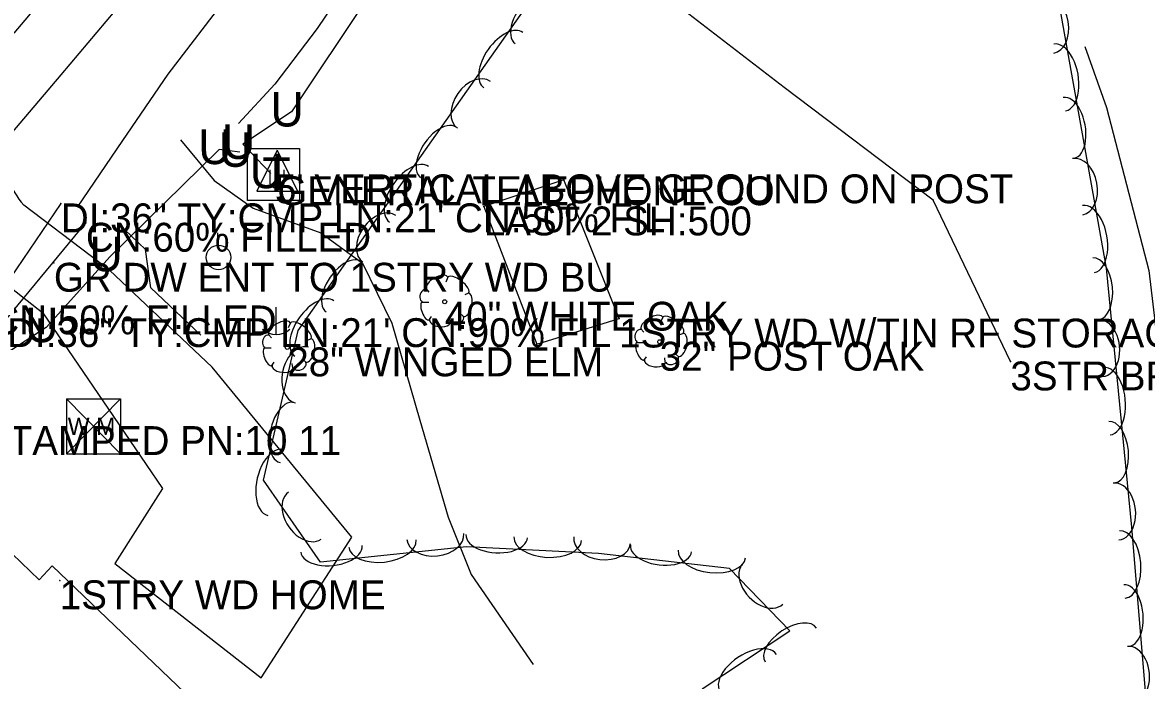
# Model space of a CAD drawing. Extents: x 1451369 to 1458940, y 1868647 to 1875095.
# Drawn here: x 1454748.2 to 1454943, y 1871712 to 1871825.9 of the extents above; entities that cross this region are included whole.
import ezdxf

# ---------------------------------------------------------------- set-up
doc = ezdxf.new("R2010")
doc.units = 0
for name, color, linetype in [('Default', 7, 'Continuous'), ('E_Const Align', 7, 'Continuous'), ('E_Label', 7, 'Continuous'), ('E_PL and Hook', 7, 'Continuous'), ('E_Property Line', 7, 'Continuous'), ('E_Proposed ROW and Easements', 7, 'Continuous'), ('E_Quarter Section Line', 7, 'Continuous'), ('E_Row Point', 7, 'Continuous'), ('E_ROW Point Number', 7, 'Continuous'), ('E_Survey Point', 7, 'Continuous'), ('E_Survey Point Number', 7, 'Continuous'), ('E_Tract Number', 7, 'Continuous'), ('S_BUILDING_ANNOT', 7, 'Continuous'), ('S_EDGE_PAVEMENT', 7, 'Continuous'), ('S_EXIST_ROW', 7, 'Continuous'), ('S_FENCE_ANNOT', 7, 'Continuous'), ('S_PARKING', 7, 'Continuous'), ('S_PAVEMENT_CROWN', 7, 'Continuous'), ('S_PRIMARY_CTL_ANNOT', 7, 'Continuous'), ('S_SIDE_DRAIN_ANNOT', 7, 'Continuous'), ('S_SURVEY_TEXT_ANNOT', 7, 'Continuous'), ('S_TELEPHONE_UTILITIES_ANNOT', 7, 'Continuous'), ('S_TRAILS', 7, 'Continuous'), ('S_TREE_ANNOT', 7, 'Continuous'), ('S_UTILITY_POLE_ANNOT', 7, 'Continuous')]:
    doc.layers.add(name, color=color, linetype=linetype)

msp = doc.modelspace()

# ---------------------------------------------------------------- linework, layer by layer
at = {"layer": 'E_Const Align'}
for p, q in [((1454782.08, 1871787.38), (1454782.08, 1871789.49)), ((1454792.13, 1871776.6), (1454792.13, 1871771.88))]:
    msp.add_line(p, q, dxfattribs=at)
msp.add_circle((1454782.2, 1871785.24), 2.13, dxfattribs=at)
msp.add_arc((1454792.19, 1871775.3), 3.41, 226.3972, 313.6028, dxfattribs=at)
at = {"layer": 'E_Label'}
msp.add_lwpolyline([(1454787.25, 1871795.09), (1454787.25, 1871804.09), (1454796.25, 1871804.09), (1454796.25, 1871795.09)], close=True, dxfattribs=at)
at = {"layer": 'E_PL and Hook'}
for p, q in [((1454754.88, 1871794.59), (1454742.84, 1871776.91)), ((1454745.56, 1871774.71), (1454759.22, 1871791.23))]:
    msp.add_line(p, q, dxfattribs=at)
at = {"layer": 'E_Property Line'}
for p, q in [((1454842.03, 1871798.65), (1454828.17, 1871794.05)), ((1454851.63, 1871774.64), (1454842.03, 1871798.65)), ((1454828.17, 1871794.05), (1454837.34, 1871770.23)), ((1454837.34, 1871770.23), (1454851.63, 1871774.64))]:
    msp.add_line(p, q, dxfattribs=at)
msp.add_lwpolyline([(1454735.46, 1871711.7), (1454767.21, 1871681.32), (1454785.83, 1871700.78), (1454753.4, 1871731.81), (1454751.13, 1871729.43), (1454744.87, 1871735.42), (1454731.07, 1871721), (1454738.01, 1871714.36)], close=True, dxfattribs=at)
at = {"layer": 'E_Proposed ROW and Easements'}
for points in [[(1454880.25, 1871814.68), (1454880.25, 1871814.73), (1454880.25, 1871814.68), (1454880.2, 1871814.68), (1454880.25, 1871814.68), (1454880.25, 1871814.63), (1454880.25, 1871814.68), (1454880.3, 1871814.68)], [(1454906.02, 1871795.15), (1454906.02, 1871795.2), (1454906.02, 1871795.15), (1454905.97, 1871795.15), (1454906.02, 1871795.15), (1454906.02, 1871795.1), (1454906.02, 1871795.15), (1454906.07, 1871795.15)], [(1454753.67, 1871784.3), (1454753.67, 1871784.35), (1454753.67, 1871784.3), (1454753.62, 1871784.3), (1454753.67, 1871784.3), (1454753.67, 1871784.25), (1454753.67, 1871784.3), (1454753.72, 1871784.3)], [(1454919.43, 1871767.21), (1454919.43, 1871767.26), (1454919.43, 1871767.21), (1454919.38, 1871767.21), (1454919.43, 1871767.21), (1454919.43, 1871767.16), (1454919.43, 1871767.21), (1454919.48, 1871767.21)]]:
    msp.add_lwpolyline(points, dxfattribs=at)
at = {"layer": 'E_Quarter Section Line'}
for p, q in [((1454755.87, 1871760.74), (1454765.21, 1871760.74)), ((1454755.87, 1871760.74), (1454755.87, 1871751.24)), ((1454755.87, 1871760.74), (1454765.21, 1871751.24)), ((1454765.21, 1871760.74), (1454755.87, 1871751.24)), ((1454765.21, 1871760.74), (1454765.21, 1871751.24)), ((1454755.87, 1871751.24), (1454765.21, 1871751.24))]:
    msp.add_line(p, q, dxfattribs=at)
at = {"layer": 'E_Row Point'}
for points in [[(1454842.03, 1871798.65), (1454842.03, 1871798.7), (1454842.03, 1871798.65), (1454841.98, 1871798.65), (1454842.03, 1871798.65), (1454842.03, 1871798.6), (1454842.03, 1871798.65), (1454842.08, 1871798.65)], [(1454828.17, 1871794.05), (1454828.17, 1871794.1), (1454828.17, 1871794.05), (1454828.12, 1871794.05), (1454828.17, 1871794.05), (1454828.17, 1871794), (1454828.17, 1871794.05), (1454828.22, 1871794.05)], [(1454851.63, 1871774.64), (1454851.63, 1871774.69), (1454851.63, 1871774.64), (1454851.58, 1871774.64), (1454851.63, 1871774.64), (1454851.63, 1871774.59), (1454851.63, 1871774.64), (1454851.68, 1871774.64)], [(1454837.34, 1871770.23), (1454837.34, 1871770.28), (1454837.34, 1871770.23), (1454837.29, 1871770.23), (1454837.34, 1871770.23), (1454837.34, 1871770.18), (1454837.34, 1871770.23), (1454837.39, 1871770.23)], [(1454754.69, 1871729.32), (1454754.69, 1871729.37), (1454754.69, 1871729.32), (1454754.64, 1871729.32), (1454754.69, 1871729.32), (1454754.69, 1871729.27), (1454754.69, 1871729.32), (1454754.74, 1871729.32)]]:
    msp.add_lwpolyline(points, dxfattribs=at)
at = {"layer": 'E_ROW Point Number'}
for p, q in [((1454821.96, 1871781.81), (1454821.57, 1871780.95)), ((1454818.16, 1871779.79), (1454818.67, 1871779.21)), ((1454825.53, 1871779.02), (1454824.87, 1871778.74)), ((1454817.51, 1871777.47), (1454818.63, 1871777.47)), ((1454818.67, 1871774.29), (1454819.13, 1871774.99)), ((1454822.35, 1871774.02), (1454822.27, 1871774.79)), ((1454824.75, 1871774.91), (1454824.29, 1871775.33)), ((1454859.21, 1871774.87), (1454858.82, 1871774.02)), ((1454794.68, 1871773.9), (1454794.29, 1871773.04)), ((1454855.41, 1871772.86), (1454855.91, 1871772.28)), ((1454790.88, 1871771.88), (1454791.38, 1871771.3)), ((1454798.24, 1871771.11), (1454797.58, 1871770.83)), ((1454862.77, 1871772.08), (1454862.11, 1871771.81)), ((1454790.22, 1871769.56), (1454791.34, 1871769.56)), ((1454854.75, 1871770.53), (1454855.87, 1871770.53)), ((1454791.38, 1871766.38), (1454791.85, 1871767.08)), ((1454795.06, 1871766.11), (1454794.99, 1871766.88)), ((1454797.47, 1871767), (1454797, 1871767.42)), ((1454855.91, 1871767.36), (1454856.38, 1871768.05)), ((1454859.59, 1871767.08), (1454859.52, 1871767.86)), ((1454862, 1871767.98), (1454861.53, 1871768.4))]:
    msp.add_line(p, q, dxfattribs=at)
msp.add_lwpolyline([(1454866, 1871710.55), (1454881.19, 1871720.56), (1454870.77, 1871731.38), (1454848.07, 1871733.96), (1454825.2, 1871735.11), (1454799.89, 1871732.45), (1454789.97, 1871746.64), (1454796, 1871772.6), (1454868.67, 1871875.67), (1454899.4, 1871918.58), (1454916.25, 1871926.31), (1454928.84, 1871911.94), (1454921.96, 1871892.98), (1454918.57, 1871861.56), (1454927.6, 1871830.59), (1454936.01, 1871783.4), (1454940.39, 1871738.54), (1454943.46, 1871701.76)], dxfattribs=at)
for centre in [(1454821.4, 1871777.56), (1454858.65, 1871770.63), (1454794.12, 1871769.65)]:
    msp.add_circle(centre, 0.341, dxfattribs=at)
for centre, major_axis, ratio, start_param, end_param in [((1454836.69, 1871826.64), (-3.08, -4.37), 0.540631, 3.141676, 6.283269), ((1454926.09, 1871825.47), (-0.87, 4.88), 0.685298, 3.141572, 6.283164), ((1454831.58, 1871819.39), (-3.38, -4.8), 0.55001, 3.141679, 6.283271), ((1454927.97, 1871816.4), (-1.03, 5.78), 0.55007, 3.14158, 6.283173), ((1454826.46, 1871811.67), (-2.86, -4.05), 0.685224, 3.141734, 6.283326), ((1454929.53, 1871807.67), (-0.94, 5.26), 0.540689, 3.14158, 6.283173), ((1454820.31, 1871803.4), (-3.08, -4.37), 0.540631, 3.141676, 6.283269), ((1454815.2, 1871796.16), (-3.38, -4.8), 0.55001, 3.141679, 6.283271), ((1454931.08, 1871797.48), (-0.87, 4.88), 0.685298, 3.141572, 6.283164), ((1454932.96, 1871788.42), (-1.03, 5.78), 0.55007, 3.14158, 6.283173), ((1454810.08, 1871788.44), (-2.86, -4.05), 0.685224, 3.141734, 6.283326), ((1454803.93, 1871780.17), (-3.08, -4.37), 0.540631, 3.141676, 6.283269), ((1454934.23, 1871779.82), (-0.52, 5.32), 0.540686, 3.14157, 6.283162), ((1454820.07, 1871780.76), (1.86, 1.08), 0.471018, 0, 3.141593), ((1454823.72, 1871780.44), (-1.81, 1.36), 0.405113, 3.141593, 6.283186), ((1454798.82, 1871772.92), (-3.38, -4.8), 0.55001, 3.141679, 6.283271), ((1454817.83, 1871778.65), (0.31, 1.03), 0.646762, 0, 3.141593), ((1454825.08, 1871777.03), (0.46, 2.04), 0.482994, 3.141593, 6.283185), ((1454818.14, 1871776), (-0.61, 1.6), 0.420543, 6.283185, 9.424777), ((1454823.56, 1871774.51), (1.09, 0.46), 0.711534, 3.141592, 6.283185), ((1454857.31, 1871773.83), (1.86, 1.08), 0.471018, 0, 3.141593), ((1454860.97, 1871773.51), (-1.81, 1.36), 0.405113, 3.141593, 6.283186), ((1454934.97, 1871769.54), (-0.48, 4.93), 0.685294, 3.141554, 6.283147), ((1454792.78, 1871772.85), (1.86, 1.08), 0.471018, 0, 3.141593), ((1454796.44, 1871772.53), (-1.81, 1.36), 0.405113, 3.141593, 6.283186), ((1454820.6, 1871774.22), (-1.83, 0.19), 0.529943, 0, 3.141593), ((1454855.08, 1871771.72), (0.31, 1.03), 0.646762, 0, 3.141593), ((1454790.55, 1871770.74), (0.31, 1.03), 0.646762, 0, 3.141593), ((1454797.79, 1871769.12), (0.46, 2.04), 0.482994, 3.141593, 6.283185), ((1454855.38, 1871769.07), (-0.61, 1.6), 0.420543, 6.283185, 9.424777), ((1454862.32, 1871770.1), (0.46, 2.04), 0.482994, 3.141593, 6.283185), ((1454790.85, 1871768.09), (-0.61, 1.6), 0.420543, 6.283185, 9.424777), ((1454796.65, 1871764.88), (-1.12, -4.83), 0.685294, 3.141775, 6.283368), ((1454796.27, 1871766.6), (1.09, 0.46), 0.711534, 3.141592, 6.283185), ((1454857.84, 1871767.28), (-1.83, 0.19), 0.529943, 0, 3.141593), ((1454860.8, 1871767.58), (1.09, 0.46), 0.711534, 3.141592, 6.283185), ((1454793.31, 1871766.31), (-1.83, 0.19), 0.529943, 0, 3.141593), ((1454936.13, 1871760.35), (-0.57, 5.84), 0.550067, 3.141569, 6.283162), ((1454794.07, 1871754.91), (-1.21, -5.21), 0.540686, 3.1417, 6.283293), ((1454936.99, 1871751.52), (-0.52, 5.32), 0.540686, 3.14157, 6.283162), ((1454792.06, 1871746.27), (-1.33, -5.72), 0.550066, 3.141704, 6.283297), ((1454937.73, 1871741.24), (-0.48, 4.93), 0.685294, 3.141554, 6.283147), ((1454797.16, 1871740.51), (2.84, -4.06), 0.685314, 3.141586, 6.283179), ((1454938.8, 1871732.07), (-0.49, 5.85), 0.550064, 3.141575, 6.283167), ((1454810.6, 1871735.71), (5.84, 0.62), 0.549999, 3.141585, 6.283177), ((1454819.78, 1871736.94), (4.93, 0.52), 0.68521, 3.14158, 6.283172), ((1454830.41, 1871736.98), (5.34, -0.27), 0.540655, 3.141483, 6.283076), ((1454839.26, 1871736.53), (5.86, -0.3), 0.550034, 3.14148, 6.283072), ((1454848.67, 1871736.29), (4.92, -0.56), 0.685252, 3.141447, 6.283039), ((1454801.78, 1871734.78), (5.32, 0.56), 0.54062, 3.141585, 6.283178), ((1454858.88, 1871734.87), (5.31, -0.6), 0.540653, 3.141506, 6.283099), ((1454867.69, 1871733.87), (5.83, -0.66), 0.550033, 3.141504, 6.283096), ((1454876.58, 1871728.78), (3.43, -3.57), 0.686146, 3.14131, 6.282903), ((1454939.54, 1871723.24), (-0.44, 5.33), 0.540684, 3.141575, 6.283168), ((1454881.39, 1871718.14), (-4.46, -2.93), 0.541823, 3.142561, 6.284153), ((1454874, 1871713.28), (-4.89, -3.22), 0.551222, 3.142592, 6.284185), ((1454940.13, 1871712.95), (-0.41, 4.94), 0.685291, 3.141563, 6.283156)]:
    msp.add_ellipse(centre, major_axis=major_axis, ratio=ratio, start_param=start_param, end_param=end_param, dxfattribs=at)
at = {"layer": 'E_Survey Point'}
for p, q in [((1454880.25, 1871814.68), (1454854.39, 1871834.51)), ((1454906.02, 1871795.15), (1454880.25, 1871814.68)), ((1454919.43, 1871767.21), (1454906.02, 1871795.15))]:
    msp.add_line(p, q, dxfattribs=at)
at = {"layer": 'E_Survey Point Number'}
for p, q in [((1454816.77, 1871843.27), (1454794.83, 1871810.44)), ((1454794.83, 1871810.44), (1454786.4, 1871804.82)), ((1454782.32, 1871803.94), (1454763.45, 1871785.37)), ((1454785.89, 1871803.47), (1454782.32, 1871803.94)), ((1454786.4, 1871804.82), (1454791.25, 1871799.75)), ((1454792.38, 1871803.82), (1454788.85, 1871796.72)), ((1454792.38, 1871803.82), (1454795.87, 1871796.72)), ((1454791.18, 1871797.96), (1454791.18, 1871800.41)), ((1454793.54, 1871800.41), (1454793.54, 1871797.96)), ((1454791.8, 1871797.31), (1454791.18, 1871797.96)), ((1454793.54, 1871797.96), (1454793, 1871797.31)), ((1454788.85, 1871796.72), (1454795.87, 1871796.72)), ((1454793, 1871797.31), (1454791.8, 1871797.31)), ((1454763.45, 1871785.37), (1454752.32, 1871773.08)), ((1454752.32, 1871773.08), (1454711.66, 1871746.73))]:
    msp.add_line(p, q, dxfattribs=at)
at = {"layer": 'E_Tract Number'}
for points in [[(1454754.88, 1871794.59), (1454754.88, 1871794.64), (1454754.88, 1871794.59), (1454754.83, 1871794.59), (1454754.88, 1871794.59), (1454754.88, 1871794.54), (1454754.88, 1871794.59), (1454754.93, 1871794.59)], [(1454759.22, 1871791.23), (1454759.22, 1871791.28), (1454759.22, 1871791.23), (1454759.17, 1871791.23), (1454759.22, 1871791.23), (1454759.22, 1871791.18), (1454759.22, 1871791.23), (1454759.27, 1871791.23)]]:
    msp.add_lwpolyline(points, dxfattribs=at)
at = {"layer": 'S_EDGE_PAVEMENT'}
msp.add_lwpolyline([(1454819.52, 1871907.39), (1454820.03, 1871906.78), (1454819.34, 1871905.12), (1454819.31, 1871904.02), (1454816.14, 1871898.87), (1454811.41, 1871892.12), (1454806.52, 1871884.57), (1454802.87, 1871879.15), (1454790.82, 1871863.04), (1454779.71, 1871847.75), (1454771.96, 1871837.84), (1454764.21, 1871827.94), (1454754.88, 1871816.87), (1454745.54, 1871805.81)], dxfattribs=at)
at = {"layer": 'S_EXIST_ROW'}
for points in [[(1454824.42, 1871859.67), (1454823.71, 1871858.48), (1454808.54, 1871838.61), (1454799.29, 1871824.85), (1454791.96, 1871815.26), (1454785.65, 1871808.4)], [(1454783.87, 1871830.65), (1454773.41, 1871816.98), (1454765.55, 1871805.47), (1454757.7, 1871793.95)], [(1454775.59, 1871805.57), (1454781.47, 1871798.53), (1454788.23, 1871793.79), (1454799.96, 1871789.52), (1454807.17, 1871784.26), (1454812.22, 1871773.85), (1454817.1, 1871757.07), (1454821.97, 1871740.28), (1454825.97, 1871730.34), (1454836.73, 1871714.78)], [(1454779.15, 1871771.77), (1454770.47, 1871779.96), (1454769.53, 1871786.61), (1454764.69, 1871791.25)]]:
    msp.add_lwpolyline(points, dxfattribs=at)
at = {"layer": 'S_PARKING'}
msp.add_lwpolyline([(1454740.86, 1871784.21), (1454751.77, 1871775.62), (1454763.99, 1871757.7), (1454772.51, 1871745.2), (1454764.23, 1871732.24), (1454789.59, 1871712.43), (1454805.28, 1871736.8), (1454781.11, 1871766.25), (1454763.29, 1871783.01), (1454748.44, 1871794.31)], dxfattribs=at)
msp.add_ellipse((1454758.85, 1871803.82), major_axis=(1.97, -14.19), ratio=0.97687, start_param=4.570422, end_param=5.304167, dxfattribs=at)
at = {"layer": 'S_PAVEMENT_CROWN'}
msp.add_lwpolyline([(1454812.39, 1871912.2), (1454802.99, 1871898.68), (1454793.59, 1871885.15), (1454781.98, 1871869.23), (1454770.38, 1871853.31), (1454755.56, 1871834.56), (1454746.72, 1871824.06)], dxfattribs=at)
at = {"layer": 'S_TRAILS'}
msp.add_lwpolyline([(1454932.3, 1871821.77), (1454936.1, 1871811.22), (1454943.39, 1871782.97), (1454949.94, 1871728.11), (1454956.19, 1871678.16)], dxfattribs=at)

# ---------------------------------------------------------------- texts
at = {"layer": 'Default'}
for p in [(1454791.2, 1871807.9), (1454782.77, 1871802.28), (1454778.69, 1871801.39), (1454782.26, 1871800.92), (1454787.62, 1871797.21), (1454759.82, 1871782.82), (1454748.69, 1871770.54)]:
    msp.add_text('U', height=6, rotation=360, dxfattribs=at).set_placement(p)
at = {"layer": 'E_Label'}
msp.add_text('T', height=6, rotation=360, dxfattribs=at).set_placement((1454789.81, 1871796.59))
at = {"layer": 'E_Quarter Section Line'}
msp.add_text('W M', height=3, rotation=360, dxfattribs=at).set_placement((1454756.08, 1871754.5))
at = {"layer": 'S_BUILDING_ANNOT'}
for s, p in [('LAST 2 SH:500', (1454828.17, 1871789.05)), ('1STRY WD W/TIN RF STORAGE', (1454851.63, 1871769.64)), ('1STRY WD HOME', (1454754.69, 1871724.32))]:
    msp.add_text(s, height=5, dxfattribs=at).set_placement(p)
at = {"layer": 'S_FENCE_ANNOT'}
msp.add_text('3STR BRB & WEB W/WD POSTS PD:CN:POOR', height=5, dxfattribs=at).set_placement((1454919.43, 1871762.21))
at = {"layer": 'S_PRIMARY_CTL_ANNOT'}
msp.add_text('PD:STD AHTD MON STAMPED PN:10 11', height=5, dxfattribs=at).set_placement((1454677.49, 1871751.02))
at = {"layer": 'S_SIDE_DRAIN_ANNOT'}
for s, p in [('DI:36" TY:CMP LN:21\' CN:50% FIL', (1454754.88, 1871789.59)), ('CN:60% FILLED', (1454759.22, 1871786.23)), ('CN:50% FILLED', (1454742.84, 1871771.91)), ('DI:36" TY:CMP LN:21\' CN:90% FIL', (1454745.56, 1871769.71))]:
    msp.add_text(s, height=5, dxfattribs=at).set_placement(p)
at = {"layer": 'S_SURVEY_TEXT_ANNOT'}
msp.add_text('GR DW ENT TO 1STRY WD BU', height=5, dxfattribs=at).set_placement((1454753.67, 1871779.3))
at = {"layer": 'S_TELEPHONE_UTILITIES_ANNOT'}
msp.add_text("5' VERTICAL ABOVE GROUND ON POST", height=5, dxfattribs=at).set_placement((1454791.97, 1871794.61))
at = {"layer": 'S_TREE_ANNOT'}
for s, p in [('40" WHITE OAK', (1454821.4, 1871772.56)), ('32" POST OAK', (1454858.65, 1871765.63)), ('28" WINGED ELM', (1454794.12, 1871764.65))]:
    msp.add_text(s, height=5, dxfattribs=at).set_placement(p)
at = {"layer": 'S_UTILITY_POLE_ANNOT'}
msp.add_text('GENERAL TELEPHONE CO', height=5, dxfattribs=at).set_placement((1454792.38, 1871794.28))

doc.saveas('drawing.dxf')
